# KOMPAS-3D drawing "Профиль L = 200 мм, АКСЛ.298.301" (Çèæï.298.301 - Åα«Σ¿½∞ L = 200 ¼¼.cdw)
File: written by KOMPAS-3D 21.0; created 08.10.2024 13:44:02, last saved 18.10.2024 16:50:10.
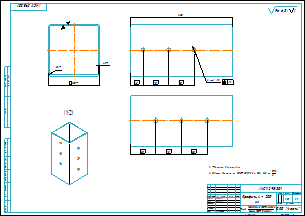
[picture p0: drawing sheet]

Sheet 1: A2, landscape

Document properties: Полное имя файла: C:\Users\Алексей Бочаров\YandexDisk\Соединения бруса\Соединения бруса\ТРИО\АКСЛ.298.301 - Профиль L = 200 мм.cdw; Автор: Алексей Бочаров; Знак неуказанной шероховатости: 4; Параметр неуказанной шероховатости: Ra 6,3; Масса: 1.514806

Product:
- Part/product: Профиль L = 200 мм  | designation АКСЛ.298.301
    Масса: 1.210897
    Форматы листов документа: A2

Title block, sheet 1: Наименование: Профиль L = 200 / мм; designation: АКСЛ.298.301; Материал: Труба  100х100х2,5 ГОСТ 8639-82 Ст3сп ГОСТ 13663-86; Масса: 1,51; Количество листов документа: 1; organisation: ООО "Аксель"; Форматы листов документа: A2; stored path: C:\Users\Алексей Бочаров\Desktop\Соединения бруса\ТРИО\Профиль L = 300 мм (1) — копия.cdw; Разработал: Бочаров; Проверил: Захаров; Утвердил: Гелетей

Views: Вид 1, Спереди, Проекционный вид 2, Проекционный вид 3, Вид 4, Изометрия
Referenced files in C:\Users\Алексей Бочаров\Desktop\Соединения бруса\ТРИО\: Профиль L = 200 мм.m3d
Referenced files in C:\Users\Алексей Бочаров\YandexDisk\Соединения бруса\Соединения бруса\ТРИО\: Профиль L = 200 мм.m3d
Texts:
  Ra 6,3
  Ra 6,3 ( )
  АКСЛ.298.300
  АКСЛ.298.301 Профиль L = 200 мм
Dimensions and other numbers on the sheet: 200; 25; 50; 6 отв.; 8; 100; 2; 2,5; 1:1; 1; 1,51

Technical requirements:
  *Размеры для справок.
  Общие допуски по ГОСТ 30893.1 - H12, h12,    IT12 2 .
